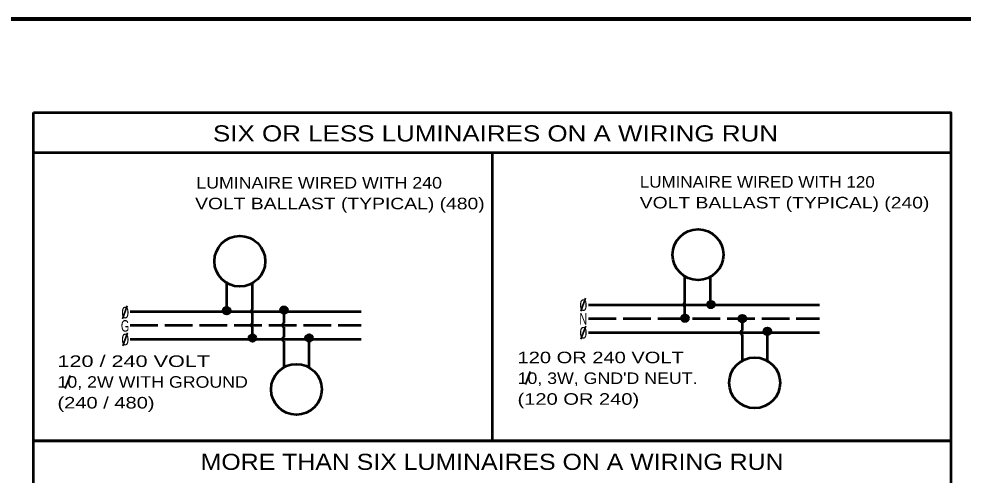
# Model space of a CAD drawing. Extents: x -217 to 639, y -295 to 249.
# Drawn here: x 237.5 to 482.9, y 123.7 to 242.4 of the extents above; entities that cross this region are included whole.
import ezdxf

# ---------------------------------------------------------------- set-up
doc = ezdxf.new("R2010")
doc.units = 0
doc.header["$LTSCALE"] = 1.2
doc.linetypes.add('LONG_DASHED', pattern=[7.5, 6, -1.5])
doc.layers.add('1', color=7, linetype='Continuous', lineweight=53)

msp = doc.modelspace()

# ---------------------------------------------------------------- linework, layer by layer
at = {"layer": '1'}
for p, q in [((241.305, 207.671), (479.623, 207.671)), ((360.464, 207.671), (360.464, 132.636)), ((410.544, 168.607), (410.544, 175.43)), ((417.238, 168.128), (417.238, 175.329)), ((291.577, 166.397), (291.577, 173.668)), ((291.577, 166.397), (291.577, 173.668)), ((298.255, 166.877), (298.255, 173.668)), ((298.255, 166.877), (298.255, 173.668)), ((385.52, 168.036), (445.52, 168.036)), ((410.561, 164.978), (410.561, 167.551)), ((266.459, 166.329), (326.459, 166.329)), ((266.459, 166.329), (326.459, 166.329)), ((298.255, 163.254), (298.255, 165.827)), ((306.363, 166.11), (306.363, 163.256)), ((425.425, 164.998), (425.425, 164.963)), ((298.255, 159.344), (298.255, 162.198)), ((298.255, 159.344), (298.255, 162.198)), ((306.363, 162.2), (306.363, 159.628)), ((425.425, 163.907), (425.425, 161.334)), ((385.52, 160.836), (445.52, 160.836)), ((425.425, 160.284), (425.425, 153.493)), ((432.035, 153.438), (432.035, 160.86)), ((266.459, 159.129), (326.459, 159.129)), ((266.459, 159.129), (326.459, 159.129)), ((306.363, 158.578), (306.363, 151.787)), ((306.363, 158.578), (306.363, 151.787)), ((312.973, 151.732), (312.973, 159.153)), ((312.973, 151.732), (312.973, 159.153))]:
    msp.add_line(p, q, dxfattribs=at)
at = {"layer": '1', "lineweight": 35}
for p, q in [((384.73, 169.748), (383.493, 166.348)), ((265.699, 167.759), (264.461, 164.36)), ((384.79, 162.48), (383.553, 159.08)), ((265.758, 160.73), (264.521, 157.33)), ((370.373, 150.684), (369.136, 147.285)), ((250.805, 149.649), (249.568, 146.25))]:
    msp.add_line(p, q, dxfattribs=at)
at = {"layer": '1', "linetype": 'LONG_DASHED'}
for p, q in [((385.52, 164.436), (445.52, 164.436)), ((266.459, 162.729), (326.459, 162.729)), ((266.459, 162.729), (326.459, 162.729))]:
    msp.add_line(p, q, dxfattribs=at)
at = {"layer": '1', "lineweight": 158}
msp.add_lwpolyline([(632.039, 242.399), (-159.661, 242.299), (-159.561, -283.701)], dxfattribs=at)
at = {"layer": '1'}
for points in [[(241.305, 218.052), (479.623, 218.052), (479.623, 132.636), (241.305, 132.636)], [(241.305, 132.636), (479.623, 132.636), (479.623, 13.402), (241.305, 13.402)]]:
    msp.add_lwpolyline(points, close=True, dxfattribs=at)
for centre, radius in [((413.977, 181.067), 6.6), ((294.916, 179.361), 6.6), ((294.916, 179.361), 6.6), ((291.536, 166.511), 0.9), ((291.536, 166.511), 0.9), ((291.536, 166.528), 0.869), ((291.536, 166.528), 0.869), ((291.536, 166.512), 0.837), ((291.536, 166.512), 0.837), ((291.528, 166.512), 0.804), ((291.52, 166.528), 0.763), ((291.507, 166.557), 0.727), ((291.495, 166.577), 0.69), ((291.491, 166.594), 0.66), ((291.483, 166.581), 0.621), ((291.475, 166.602), 0.579), ((291.466, 166.594), 0.545), ((291.454, 166.635), 0.509), ((291.446, 166.643), 0.476), ((291.429, 166.651), 0.429), ((291.434, 166.651), 0.4), ((291.425, 166.684), 0.357), ((291.413, 166.704), 0.32), ((291.409, 166.713), 0.283), ((291.405, 166.717), 0.246), ((291.393, 166.717), 0.209), ((291.376, 166.721), 0.16), ((291.376, 166.721), 0.119), ((306.391, 166.648), 0.9), ((306.391, 166.648), 0.9), ((306.391, 166.664), 0.869), ((306.391, 166.664), 0.869), ((306.391, 166.648), 0.837), ((306.391, 166.648), 0.837), ((306.383, 166.648), 0.804), ((306.375, 166.664), 0.763), ((306.362, 166.693), 0.727), ((306.35, 166.714), 0.69), ((306.346, 166.73), 0.66), ((306.338, 166.718), 0.621), ((306.33, 166.738), 0.579), ((306.321, 166.73), 0.545), ((306.309, 166.771), 0.509), ((306.301, 166.779), 0.476), ((306.284, 166.787), 0.429), ((306.289, 166.787), 0.4), ((306.28, 166.82), 0.357), ((306.268, 166.841), 0.32), ((306.264, 166.849), 0.283), ((306.26, 166.853), 0.246), ((306.248, 166.853), 0.209), ((306.231, 166.857), 0.16), ((306.231, 166.857), 0.119), ((306.235, 166.853), 0.0657), ((306.227, 166.861), 0.0249), ((410.433, 168.431), 0.0249), ((417.335, 168.105), 0.9), ((417.335, 168.122), 0.869), ((417.335, 168.106), 0.837), ((417.326, 168.106), 0.804), ((417.318, 168.122), 0.763), ((417.306, 168.151), 0.727), ((417.294, 168.172), 0.69), ((417.289, 168.188), 0.66), ((417.281, 168.176), 0.621), ((417.273, 168.196), 0.579), ((417.265, 168.188), 0.545), ((417.253, 168.229), 0.509), ((417.244, 168.237), 0.476), ((417.228, 168.245), 0.429), ((417.232, 168.245), 0.4), ((417.224, 168.278), 0.357), ((417.212, 168.299), 0.32), ((417.207, 168.307), 0.283), ((417.203, 168.311), 0.246), ((417.191, 168.311), 0.209), ((417.175, 168.315), 0.16), ((417.175, 168.315), 0.119), ((417.179, 168.311), 0.0657), ((291.38, 166.717), 0.0657), ((291.372, 166.725), 0.0249), ((410.597, 164.55), 0.9), ((410.597, 164.567), 0.869), ((410.597, 164.55), 0.837), ((410.589, 164.55), 0.804), ((410.581, 164.567), 0.763), ((410.569, 164.595), 0.727), ((410.556, 164.616), 0.69), ((410.552, 164.632), 0.66), ((410.544, 164.62), 0.621), ((410.536, 164.64), 0.579), ((410.528, 164.632), 0.545), ((410.515, 164.673), 0.509), ((410.507, 164.681), 0.476), ((410.491, 164.69), 0.429), ((410.495, 164.69), 0.4), ((410.487, 164.722), 0.357), ((410.474, 164.743), 0.32), ((410.47, 164.751), 0.283), ((410.466, 164.755), 0.246), ((410.454, 164.755), 0.209), ((410.437, 164.759), 0.16), ((410.437, 164.759), 0.119), ((410.441, 164.755), 0.0657), ((425.49, 164.424), 0.9), ((425.49, 164.441), 0.869), ((425.49, 164.424), 0.837), ((425.481, 164.424), 0.804), ((425.473, 164.441), 0.763), ((425.461, 164.47), 0.727), ((425.449, 164.49), 0.69), ((425.445, 164.507), 0.66), ((425.436, 164.494), 0.621), ((425.428, 164.515), 0.579), ((425.42, 164.507), 0.545), ((425.408, 164.548), 0.509), ((425.399, 164.556), 0.476), ((425.383, 164.564), 0.429), ((425.387, 164.564), 0.4), ((425.379, 164.597), 0.357), ((425.367, 164.617), 0.32), ((425.363, 164.625), 0.283), ((425.358, 164.63), 0.246), ((425.346, 164.63), 0.209), ((425.33, 164.634), 0.16), ((425.33, 164.634), 0.119), ((425.334, 164.63), 0.0657), ((425.326, 164.638), 0.0249), ((431.994, 161.131), 0.9), ((431.994, 161.148), 0.869), ((431.994, 161.132), 0.837), ((431.986, 161.132), 0.804), ((298.214, 159.424), 0.9), ((298.214, 159.424), 0.9), ((298.214, 159.441), 0.869), ((298.214, 159.441), 0.869), ((298.214, 159.425), 0.837), ((298.206, 159.425), 0.804), ((298.198, 159.441), 0.763), ((298.185, 159.47), 0.727), ((298.173, 159.49), 0.69), ((298.169, 159.507), 0.66), ((298.161, 159.495), 0.621), ((298.152, 159.515), 0.579), ((298.144, 159.507), 0.545), ((298.132, 159.548), 0.509), ((298.124, 159.556), 0.476), ((298.107, 159.564), 0.429), ((298.111, 159.564), 0.4), ((298.103, 159.597), 0.357), ((298.091, 159.618), 0.32), ((298.087, 159.626), 0.283), ((298.083, 159.63), 0.246), ((298.07, 159.63), 0.209), ((298.054, 159.634), 0.16), ((298.054, 159.634), 0.119), ((298.058, 159.63), 0.0657), ((298.05, 159.638), 0.0249), ((312.933, 159.424), 0.9), ((312.933, 159.424), 0.9), ((312.933, 159.441), 0.869), ((312.933, 159.441), 0.869), ((312.933, 159.425), 0.837), ((312.933, 159.425), 0.837), ((312.924, 159.425), 0.804), ((312.924, 159.425), 0.804), ((312.916, 159.441), 0.763), ((312.904, 159.47), 0.727), ((312.892, 159.49), 0.69), ((312.887, 159.507), 0.66), ((312.879, 159.495), 0.621), ((312.871, 159.515), 0.579), ((312.863, 159.507), 0.545), ((312.851, 159.548), 0.509), ((312.842, 159.556), 0.476), ((312.826, 159.564), 0.429), ((312.83, 159.564), 0.4), ((312.822, 159.597), 0.357), ((312.81, 159.618), 0.32), ((312.805, 159.626), 0.283), ((312.801, 159.63), 0.246), ((312.789, 159.63), 0.209), ((312.773, 159.634), 0.16), ((312.773, 159.634), 0.119), ((312.777, 159.63), 0.0657), ((312.769, 159.638), 0.0249), ((431.977, 161.148), 0.763), ((431.965, 161.177), 0.727), ((431.953, 161.197), 0.69), ((431.949, 161.214), 0.66), ((431.94, 161.201), 0.621), ((431.932, 161.222), 0.579), ((431.924, 161.214), 0.545), ((431.912, 161.255), 0.509), ((431.904, 161.263), 0.476), ((431.887, 161.271), 0.429), ((431.891, 161.271), 0.4), ((431.883, 161.304), 0.357), ((431.871, 161.324), 0.32), ((431.867, 161.332), 0.283), ((431.863, 161.337), 0.246), ((431.85, 161.337), 0.209), ((431.834, 161.341), 0.16), ((431.834, 161.341), 0.119), ((431.838, 161.337), 0.0657), ((431.83, 161.345), 0.0249), ((309.635, 146.039), 6.6), ((309.635, 146.039), 6.6), ((428.696, 147.745), 6.6)]:
    msp.add_circle(centre, radius, dxfattribs=at)
for centre in [(298.418, 166.355), (298.418, 166.355), (410.725, 168.079), (425.623, 164.435), (298.452, 162.726), (306.561, 162.728), (306.561, 162.728), (306.527, 159.1), (306.527, 159.1), (425.588, 160.806)]:
    msp.add_arc(centre, 0.558, 108.90604, 251.09396, dxfattribs=at)

# ---------------------------------------------------------------- texts
for s, height, width, p in [('SIX OR LESS LUMINAIRES ON A WIRING RUN', 4.2, 1.2, (287.953, 210.513)), ('LUMINAIRE WIRED WITH 240', 3, 1.15, (283.62, 198.278)), ('LUMINAIRE WIRED WITH 120', 3, 1.1, (398.846, 198.499)), ('VOLT BALLAST (TYPICAL) (480)', 3, 1.25, (283.304, 192.878)), ('VOLT BALLAST (TYPICAL) (240)', 3, 1.25, (398.846, 193.099)), ('0', 3, 0.9, (383.178, 166.448)), ('0', 3, 0.9, (264.147, 164.512)), ('N', 3, 0.7, (383.148, 162.869)), ('G', 3, 0.7, (264.026, 161.053)), ('0', 3, 0.9, (383.178, 159.26)), ('0', 3, 0.9, (264.147, 157.504)), ('120 / 240 VOLT', 3, 1.4, (247.546, 151.867)), ('120 OR 240 VOLT', 3, 1.3, (367.088, 152.839)), ("10, 3W, GND'D NEUT.", 3, 1.15, (367.088, 147.439)), ('10, 2W WITH GROUND', 3, 1.15, (247.546, 146.466)), ('(120 OR 240)', 3, 1.3, (367.088, 142.039)), ('(240 / 480)', 3, 1.3, (247.546, 141.067)), ('MORE THAN SIX LUMINAIRES ON A WIRING RUN', 4.2, 1.15, (284.754, 125.097))]:
    msp.add_text(s, height=height, dxfattribs=dict(at, width=width)).set_placement(p)

doc.saveas('drawing.dxf')
